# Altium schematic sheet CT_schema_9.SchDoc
size 391 x 238 mm
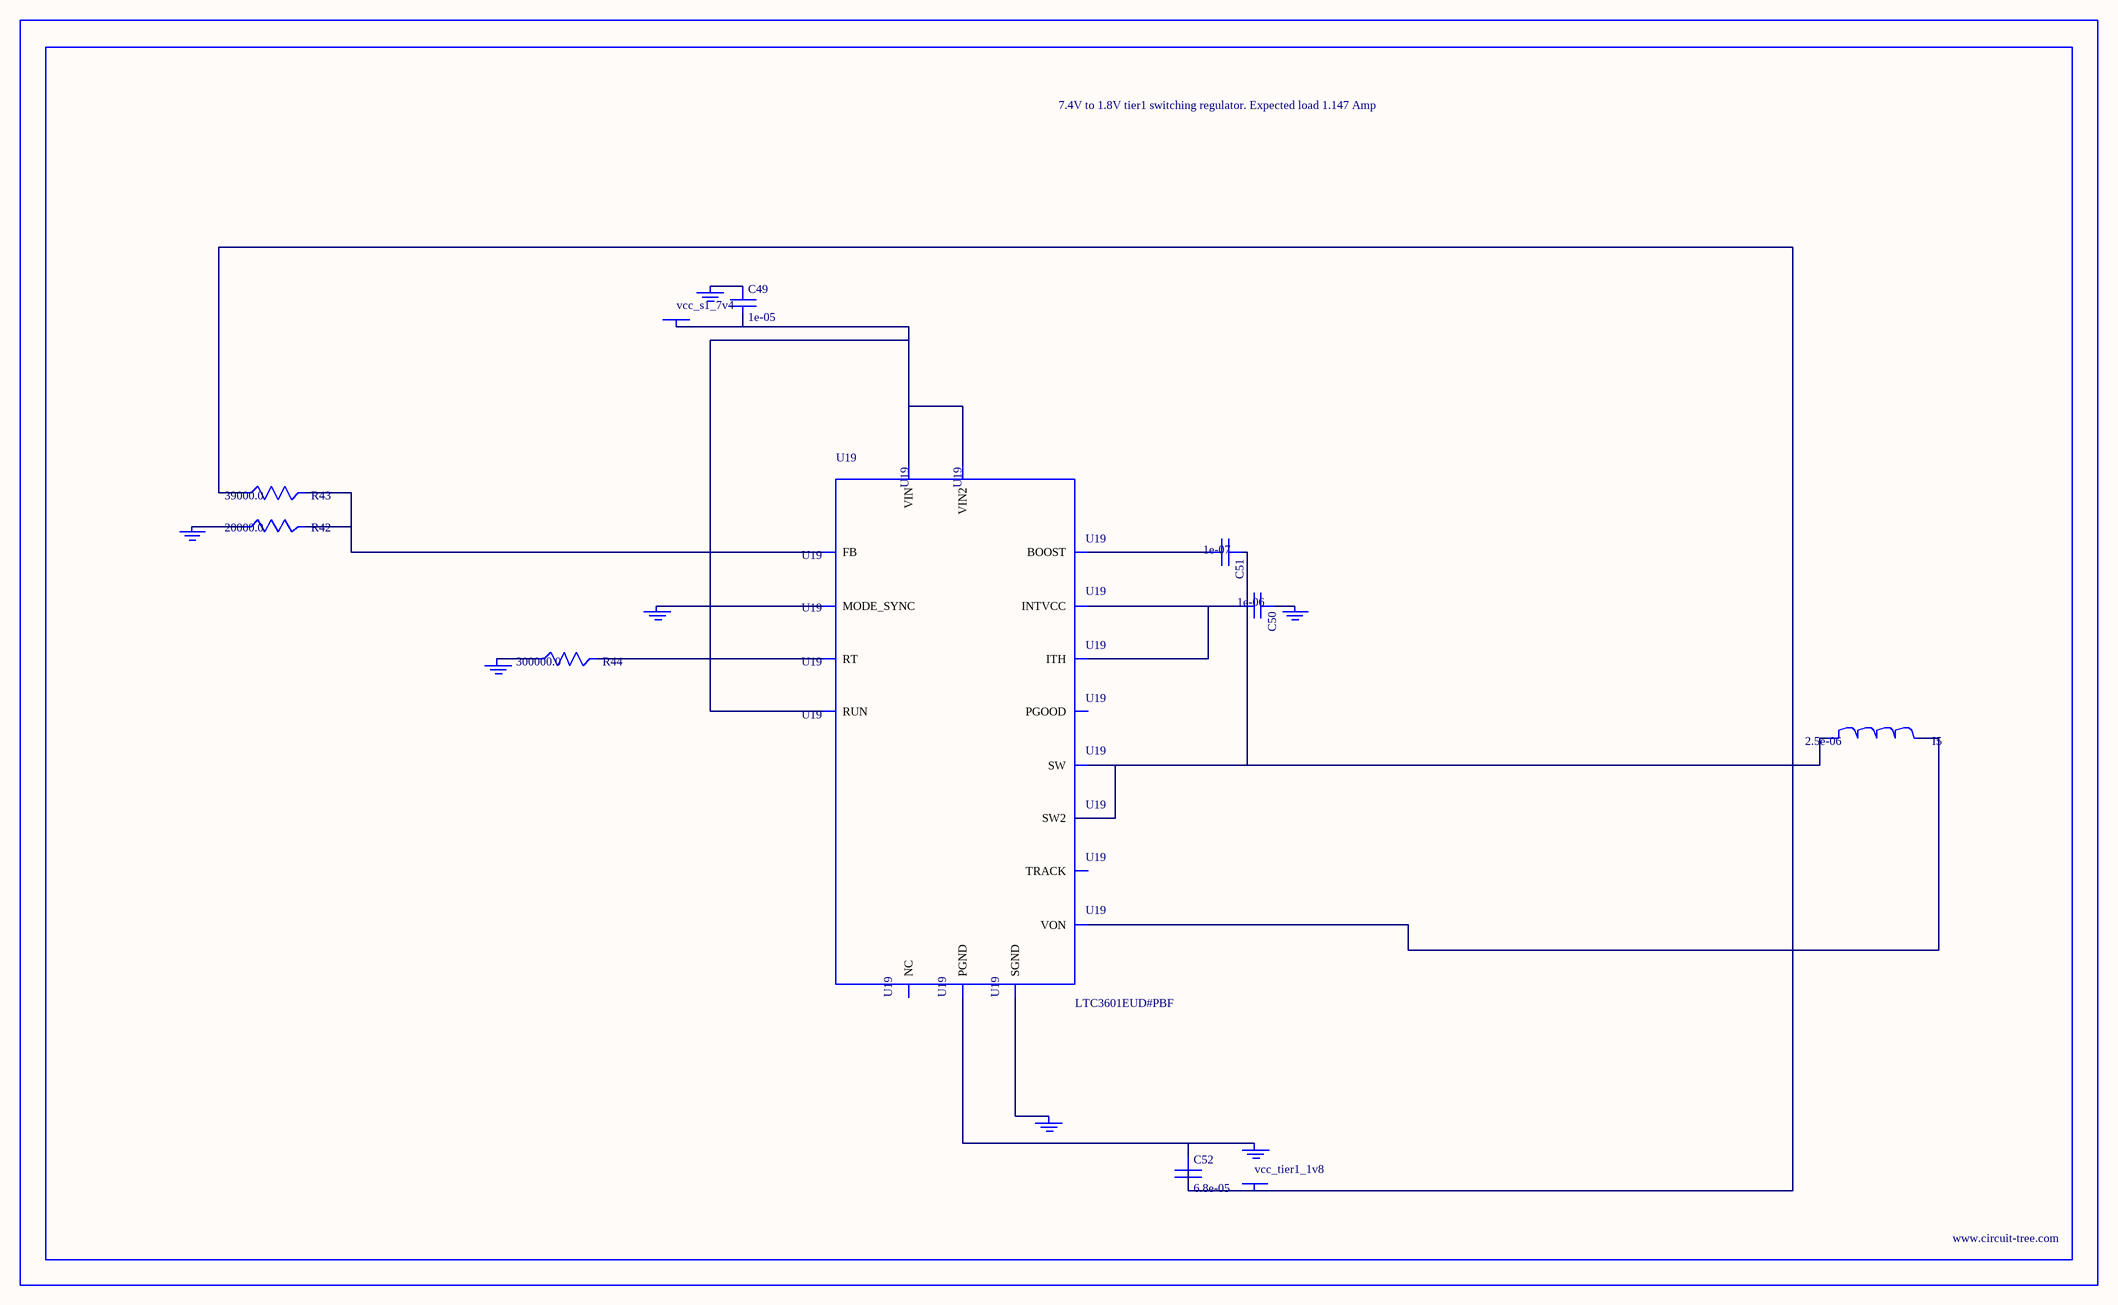
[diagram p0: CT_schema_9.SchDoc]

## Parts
BORDER8  (no value)
C49  1e-05  [C0805]
C50  1e-06  [C0603]
C51  1e-07  [C0402]
C52  6.8e-05  [2220]
GND_INSTANCE_8_0  (no value)
GND_INSTANCE_8_1  (no value)
GND_INSTANCE_8_2  (no value)
GND_INSTANCE_8_3  (no value)
GND_INSTANCE_8_4  (no value)
GND_INSTANCE_8_5  (no value)
GND_INSTANCE_8_6  (no value)
I5  2.5e-06  [DR1040]
POWER_INSTANCE_8_0  vcc_s1_7v4
POWER_INSTANCE_8_1  vcc_tier1_1v8
R42  20000.0  [R0603]
R43  39000.0  [R0603]
R44  300000.0  [R0603]
U19  LTC3601EUD#PBF  [QFN-16_EP]

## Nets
NetC49_1: C49.1 GND_INSTANCE_8_5.0(GND)
NetC49_2: C49.2 POWER_INSTANCE_8_0.0(PWR) U19.14(RUN) U19.15(VIN) U19.16(VIN2)
NetC50_1: C50.1 GND_INSTANCE_8_1.0(GND)
NetC50_2: C50.2 U19.7(INTVCC) U19.12(ITH)
NetC51_1: C51.1 I5.1 U19.3(SW) U19.4(SW2)
NetC51_2: C51.2 U19.6(BOOST)
NetC52_1: C52.1 GND_INSTANCE_8_6.0(GND) U19.17(PGND)
NetC52_2: C52.2 I5.2 POWER_INSTANCE_8_1.0(PWR) R43.1 U19.8(VON)
NetGND_INSTANCE_8_0_0: GND_INSTANCE_8_0.0(GND) U19.1(MODE_SYNC)
NetGND_INSTANCE_8_2_0: GND_INSTANCE_8_2.0(GND) U19.9(SGND)
NetGND_INSTANCE_8_3_0: GND_INSTANCE_8_3.0(GND) R44.1
NetGND_INSTANCE_8_4_0: GND_INSTANCE_8_4.0(GND) R42.1
NetR42_2: R42.2 R43.2 U19.11(FB)
NetR44_2: R44.2 U19.10(RT)

Not connected (* = marked no-connect by the designer): U19 2(PGOOD) 5(NC) 13(TRACK)

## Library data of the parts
BORDER8 = BORDER_PAGE8
C49 = C0805C106K8RACTU
C50 = C0603C105K3RACTU
C51 = C0402C104K3RACTU
C52 = C5750X5R1A686M
GND_INSTANCE_8_0-GND_INSTANCE_8_6 = GND
I5 = DR1040-2R5-R
POWER_INSTANCE_8_0 POWER_INSTANCE_8_1 = PWR
R42 = RC0603JR-0720KL
R43 = RC0603JR-0739KL
R44 = RC0603JR-07300KL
